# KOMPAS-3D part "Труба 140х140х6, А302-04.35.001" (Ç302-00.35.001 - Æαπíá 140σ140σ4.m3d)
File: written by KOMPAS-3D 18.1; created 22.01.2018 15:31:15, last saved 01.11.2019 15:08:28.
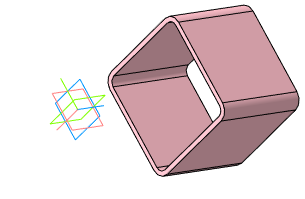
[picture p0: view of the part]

Document properties: Автор: Милов; Полное имя файла: D:\Мембранные насосы\Мембранный электропривод\А302-00.00.000 - ASTRA-302 (МЭ200)\3Д\А302-00.35.001 - Труба 140х140х4.m3d

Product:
- Part/product: Труба 140х140х6  | designation А302-04.35.001
    Масса: 4.6797
    Раздел спецификации: Детали
    Форматы листов документа: A4
- Part/product: Труба 140х140х4  | designation А302-00.35.001
    Масса: 4.39548
    Раздел спецификации: Детали
    Форматы листов документа: A4
  - Component: Труба 140х140х4  | designation А302-00.35.001  | Масса: 4.4; Раздел спецификации: Детали; Форматы листов документа: A4
- Part/product: Труба 140х140х6  | designation А302-05.35.001
    Масса: 2.81713
    Раздел спецификации: Детали
    Форматы листов документа: A4

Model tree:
1. Эскиз:1
2. Операция выдавливания:1  (labels: v482_v28)
     Толщина стенки 2 = 4; Расстояние 1 = 265
3. Элемент выдавливания:1  (with: Операция выдавливания:1)
     Расстояние 2 = 62
4. Эскиз:3  (with: Элемент выдавливания:1)
5. Элемент выдавливания:2  (labels: v482_v28)
     Расстояние 2 = 203
6. Элемент выдавливания:3  (with: Элемент выдавливания:1)
     Расстояние 2 = 80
